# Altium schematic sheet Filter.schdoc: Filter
size A4; Organization: Altium Limited; Address1: L3, 12a Rodborough Rd; Address2: Frenchs Forest; Address3: NSW; Address4: Australia 2086; DocumentNumber: 1; SheetNumber: 1; SheetTotal: 1
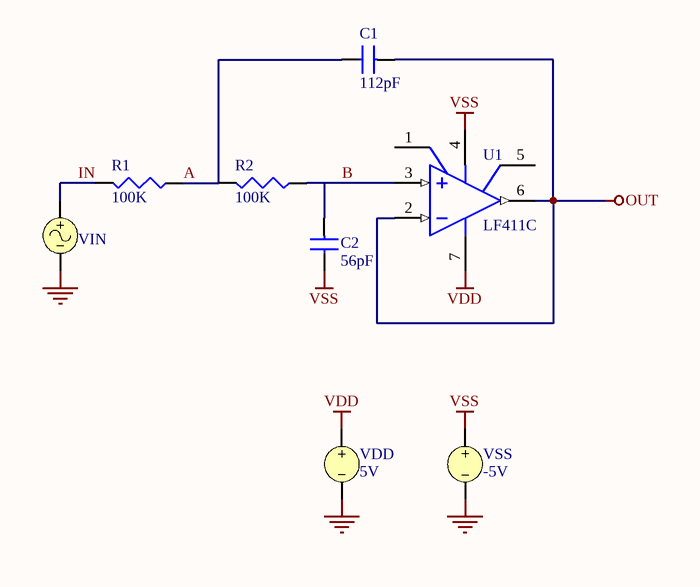
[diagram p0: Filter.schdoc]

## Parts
C1  112pF
C2  56pF
R1  100K
R2  100K
U1  LF411C
VDD  5V
VIN  VSIN  (value not drawn)
VSS  -5V

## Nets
GND: VDD.2 VIN.2 VSS.2
OUT: C1.1 U1.2(IN-) U1.6(OUT)
VDD: U1.7(VCC+) VDD.1
VSS: C2.2 U1.4(VCC_-) VSS.1
A: C1.2 R1.2(BOT) R2.1(TOP)
B: C2.1 R2.2(BOT) U1.3(IN+)
IN: R1.1(TOP) VIN.1

Not connected (* = marked no-connect by the designer): U1 1(OS_NULL-) 5(OS_NULL+)

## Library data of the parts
C1 C2 = CAP: Capacitor
R1 R2 = RES: Resistor
U1 = LF411C: Wide Bandwidth JFET Input Operational Amplifier
VDD VSS = VSRC: Voltage Source
VIN = VSIN: Sinusoidal Voltage Source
